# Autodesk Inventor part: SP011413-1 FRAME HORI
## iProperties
Created: 2013-01
Part Number: SP011413-1 FRAME HORI
Material: Aluminum-6061
Description: PROFILE 45X45 F
Document SubType Name: Modeling
Designer: Administrator
Stock Number: 20.1033 PROFILE 45X45 F
Density: 2.71 g/cm^3
Mass: 3088.7 g
Surface Area: 8296.43 cm^2
Volume: 1139.74 cm^3
FINISH: CLEAR ANODIZED
Author: Administrator
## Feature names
1. Extrusion1
